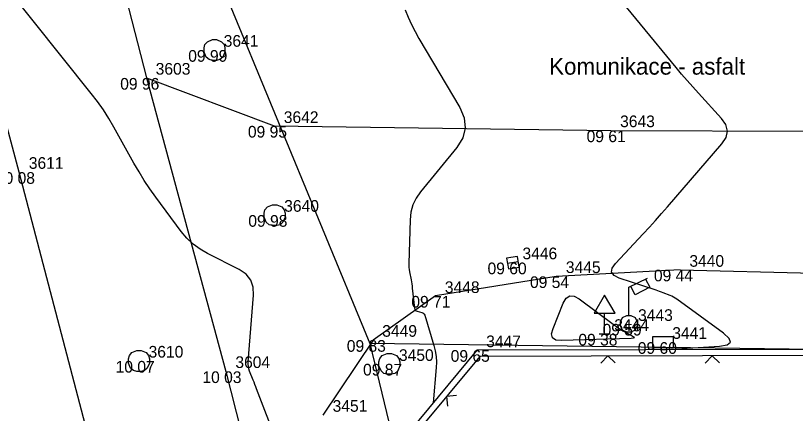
# Model space of a CAD drawing. Extents: x -703403 to -701924, y -1022520 to -1021856.
# Drawn here: x -702667.24 to -702648.55, y -1022343.16 to -1022333.61 of the extents above; entities that cross this region are included whole.
import ezdxf

# ---------------------------------------------------------------- set-up
doc = ezdxf.new("R2010")
doc.units = 0
for name, color, linetype in [('Ex_Major Contours', 7, 'Continuous'), ('Ex_Minor Contours', 7, 'Continuous'), ('Z_body', 7, 'Continuous'), ('Z_body_cisla', 7, 'Continuous'), ('Z_body_vysky_redukovane', 7, 'Continuous'), ('Z_dopravni_znacky', 7, 'Continuous'), ('Z_katastr_hranice', 7, 'Continuous'), ('Z_komunikace', 7, 'Continuous'), ('Z_komunikace_osa', 7, 'Continuous'), ('Z_pilire', 7, 'Continuous'), ('Z_ploty', 7, 'Continuous'), ('Z_ploty_znacky', 7, 'Continuous'), ('Z_popisy', 7, 'Continuous'), ('Z_site_kanalizace_znaky', 7, 'Continuous'), ('Z_site_vo_znaky', 7, 'Continuous'), ('Z_vdz13_prerusovana', 7, 'Continuous'), ('Z_VDZ_25_prerus', 7, 'Continuous')]:
    doc.layers.add(name, color=color, linetype=linetype)

# ---------------------------------------------------------------- blocks, each defined once
blk = doc.blocks.new('POINT_DISPLAY')
blk.add_line((0, 0), (0, 0))
blk = doc.blocks.new('Z13')
for p, q in [((0, 0.88), (0.45, 1.1)), ((0.4, 1.07), (0.5, 0.88)), ((0, 0.2), (0, 0.88)), ((0.15, 0.7), (0.05, 0.9)), ((0.5, 0.88), (0.15, 0.7)), ((-0.15, 0.15), (-0.05, 0.2)), ((-0.05, 0.2), (0.05, 0.2)), ((0.05, 0.2), (0.15, 0.15)), ((-0.2, 0.05), (-0.15, 0.15)), ((-0.2, -0.05), (-0.2, 0.05)), ((0.15, 0.15), (0.2, 0.05)), ((0.2, 0.05), (0.2, -0.05)), ((-0.15, -0.15), (-0.2, -0.05)), ((-0.05, -0.2), (-0.15, -0.15)), ((0.15, -0.15), (0.05, -0.2)), ((0.2, -0.05), (0.15, -0.15)), ((0.05, -0.2), (-0.05, -0.2))]:
    blk.add_line(p, q)
blk = doc.blocks.new('Z666')
for p, q in [((-0.25, 0.13), (-0.25, -0.13)), ((0.25, 0.13), (-0.25, 0.13)), ((0.25, -0.13), (0.25, 0.13)), ((-0.25, -0.13), (0.25, -0.13))]:
    blk.add_line(p, q)
blk = doc.blocks.new('Z620')
for p, q in [((-0.23, 0.13), (-0.17, 0.2)), ((-0.17, 0.2), (-0.05, 0.25)), ((-0.05, 0.25), (0.05, 0.25)), ((0.05, 0.25), (0.17, 0.2)), ((0.17, 0.2), (0.23, 0.13)), ((-0.25, 0.05), (-0.23, 0.13)), ((-0.25, -0.05), (-0.25, 0.05)), ((0.23, 0.13), (0.25, 0.05)), ((0.25, 0.05), (0.25, -0.05)), ((-0.2, -0.17), (-0.25, -0.05)), ((-0.13, -0.23), (-0.2, -0.17)), ((0.2, -0.17), (0.13, -0.23)), ((0.25, -0.05), (0.2, -0.17)), ((-0.05, -0.25), (-0.13, -0.23)), ((0.05, -0.25), (-0.05, -0.25)), ((0.13, -0.23), (0.05, -0.25))]:
    blk.add_line(p, q)
blk = doc.blocks.new('Z46260')
for p, q in [((0.13, 0.13), (-0.13, 0.13)), ((-0.13, 0.13), (-0.13, -0.13)), ((0.13, 0), (-0.13, 0)), ((0.13, -0.13), (0.13, 0.13)), ((-0.13, -0.13), (0.13, -0.13))]:
    blk.add_line(p, q)
blk = doc.blocks.new('Z527')
for p, q in [((0, 0.93), (-0.25, 0.5)), ((0.25, 0.5), (0, 0.93)), ((-0.25, 0.5), (0.25, 0.5)), ((0, 0), (0, 0.5)), ((-0.13, 0), (0.13, 0))]:
    blk.add_line(p, q)
blk = doc.blocks.new('Z212')
for p, q in [((-0.17, 0.17), (0, 0)), ((0, 0), (0.17, 0.17))]:
    blk.add_line(p, q)

msp = doc.modelspace()

# ---------------------------------------------------------------- linework, layer by layer
at = {"layer": 'Ex_Major Contours'}
msp.add_lwpolyline([(-702660.969, -1022343.856), (-702661.46, -1022342.572), (-702661.481, -1022342.519), (-702661.501, -1022342.465), (-702661.522, -1022342.412), (-702661.543, -1022342.358), (-702661.628, -1022342.144), (-702661.646, -1022342.09), (-702661.658, -1022342.036), (-702661.663, -1022341.98), (-702661.661, -1022341.923), (-702661.532, -1022340.323), (-702661.541, -1022340.126), (-702661.601, -1022339.958), (-702661.713, -1022339.819), (-702661.877, -1022339.708), (-702662.635, -1022339.325), (-702662.817, -1022339.219), (-702662.983, -1022339.095), (-702663.133, -1022338.953), (-702663.267, -1022338.792), (-702663.878, -1022337.968), (-702664.018, -1022337.771), (-702664.152, -1022337.57), (-702664.279, -1022337.366), (-702664.4, -1022337.156), (-702664.879, -1022336.292), (-702665.002, -1022336.081), (-702665.134, -1022335.875), (-702665.274, -1022335.674), (-702665.422, -1022335.48), (-702667.51, -1022332.859)], dxfattribs=at)
at = {"layer": 'Ex_Minor Contours'}
for points in [[(-702651.778, -1022341.631), (-702650.365, -1022341.542), (-702650.183, -1022341.512), (-702650.107, -1022341.451), (-702650.138, -1022341.358), (-702650.275, -1022341.234), (-702651.39, -1022340.416), (-702651.428, -1022340.391), (-702651.467, -1022340.368), (-702651.507, -1022340.347), (-702651.548, -1022340.329), (-702651.717, -1022340.263), (-702651.76, -1022340.247), (-702651.802, -1022340.231), (-702651.845, -1022340.216), (-702651.888, -1022340.202), (-702652.77, -1022339.912), (-702652.896, -1022339.85), (-702652.953, -1022339.771), (-702652.941, -1022339.673), (-702652.86, -1022339.558), (-702652.195, -1022338.85), (-702652.046, -1022338.69), (-702651.899, -1022338.528), (-702651.754, -1022338.365), (-702651.611, -1022338.2), (-702650.309, -1022336.69), (-702650.21, -1022336.536), (-702650.178, -1022336.383), (-702650.214, -1022336.23), (-702650.318, -1022336.079), (-702650.87, -1022335.476), (-702651.007, -1022335.324), (-702651.142, -1022335.171), (-702651.275, -1022335.015), (-702651.405, -1022334.858), (-702653.116, -1022332.77)], [(-702657.902, -1022333.475), (-702657.83, -1022333.651), (-702657.751, -1022333.824), (-702657.665, -1022333.994), (-702657.571, -1022334.16), (-702656.59, -1022335.822), (-702656.483, -1022336.07), (-702656.46, -1022336.312), (-702656.519, -1022336.548), (-702656.663, -1022336.777), (-702657.53, -1022337.839), (-702657.636, -1022337.992), (-702657.714, -1022338.156), (-702657.762, -1022338.33), (-702657.782, -1022338.516), (-702657.812, -1022339.56), (-702657.812, -1022339.61), (-702657.81, -1022339.66), (-702657.805, -1022339.709), (-702657.797, -1022339.758), (-702657.76, -1022339.954), (-702657.751, -1022340.004), (-702657.744, -1022340.053), (-702657.737, -1022340.102), (-702657.731, -1022340.152), (-702657.676, -1022340.636), (-702657.67, -1022340.662), (-702657.658, -1022340.682), (-702657.639, -1022340.697), (-702657.614, -1022340.707), (-702657.503, -1022340.734), (-702657.478, -1022340.743), (-702657.457, -1022340.758), (-702657.442, -1022340.777), (-702657.431, -1022340.802), (-702657.213, -1022341.529), (-702657.18, -1022341.66), (-702657.16, -1022341.793), (-702657.152, -1022341.926), (-702657.158, -1022342.061), (-702657.23, -1022342.905)]]:
    msp.add_lwpolyline(points, dxfattribs=at)
msp.add_lwpolyline([(-702654.289, -1022341.399), (-702654.368, -1022341.345), (-702654.391, -1022341.253), (-702654.358, -1022341.121), (-702654.113, -1022340.517), (-702654.043, -1022340.397), (-702653.955, -1022340.339), (-702653.851, -1022340.344), (-702653.729, -1022340.41), (-702652.888, -1022341.038), (-702652.838, -1022341.075), (-702652.786, -1022341.11), (-702652.734, -1022341.143), (-702652.681, -1022341.174), (-702652.464, -1022341.298), (-702652.425, -1022341.325), (-702652.414, -1022341.345), (-702652.433, -1022341.357), (-702652.481, -1022341.363), (-702654.154, -1022341.413)], close=True, dxfattribs=at)
at = {"layer": 'Z_katastr_hranice'}
for p, q in [((-702668.61, -1022317.56), (-702658.75, -1022341.48)), ((-702629.64, -1022341.87), (-702658.75, -1022341.48)), ((-702658.75, -1022341.48), (-702651.59, -1022370.87))]:
    msp.add_line(p, q, dxfattribs=at)
at = {"layer": 'Z_komunikace'}
for p, q in [((-702651.31, -1022339.71), (-702654.28, -1022339.87)), ((-702651.31, -1022339.71), (-702644.5, -1022339.89)), ((-702654.28, -1022339.87), (-702657.17, -1022340.34)), ((-702657.17, -1022340.34), (-702658.67, -1022341.4)), ((-702658.67, -1022341.4), (-702659.87, -1022343.2))]:
    msp.add_line(p, q, dxfattribs=at)
at = {"layer": 'Z_komunikace_osa'}
for p, q in [((-702664.1, -1022335.11), (-702661.04, -1022336.26)), ((-702661.04, -1022336.26), (-702652.97, -1022336.37)), ((-702652.97, -1022336.37), (-702644.72, -1022336.4))]:
    msp.add_line(p, q, dxfattribs=at)
at = {"layer": 'Z_ploty'}
for p, q in [((-702656.18, -1022341.64), (-702658.28, -1022344.17)), ((-702646.79, -1022341.62), (-702656.18, -1022341.64)), ((-702646.79, -1022341.77), (-702656.11, -1022341.79)), ((-702656.11, -1022341.79), (-702658.12, -1022344.21))]:
    msp.add_line(p, q, dxfattribs=at)
at = {"layer": 'Z_vdz13_prerusovana'}
for p, q in [((-702667.15, -1022337.37), (-702668.59, -1022332.01)), ((-702665.25, -1022344.64), (-702667.15, -1022337.37))]:
    msp.add_line(p, q, dxfattribs=at)
at = {"layer": 'Z_VDZ_25_prerus'}
for p, q in [((-702665.97, -1022327.85), (-702664.1, -1022335.11)), ((-702664.1, -1022335.11), (-702662.2, -1022342.15)), ((-702662.2, -1022342.15), (-702661.45, -1022345.12))]:
    msp.add_line(p, q, dxfattribs=at)

# ---------------------------------------------------------------- block references
at = {"layer": 'Z_body'}
for p in [(-702662.47, -1022334.44), (-702664.1, -1022335.11), (-702661.04, -1022336.26), (-702652.97, -1022336.37), (-702667.15, -1022337.37), (-702661.03, -1022338.4), (-702655.32, -1022339.54), (-702651.31, -1022339.71), (-702654.28, -1022339.87), (-702657.17, -1022340.34), (-702652.54, -1022341.01), (-702658.67, -1022341.4), (-702653.12, -1022341.25), (-702651.72, -1022341.45), (-702656.18, -1022341.64), (-702664.28, -1022341.9), (-702662.2, -1022342.15), (-702658.28, -1022341.97)]:
    msp.add_blockref('POINT_DISPLAY', p, dxfattribs=at)
at = {"layer": 'Z_dopravni_znacky'}
msp.add_blockref('Z527', (-702653.12, -1022341.25), dxfattribs=at)
at = {"layer": 'Z_pilire'}
msp.add_blockref('Z666', (-702651.72, -1022341.45), dxfattribs=at)
at = {"layer": 'Z_ploty_znacky'}
for p, rotation in [((-702653.04, -1022341.78), -179.90000000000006), ((-702650.54, -1022341.78), -179.90000000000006), ((-702656.91, -1022342.75), -129.69999999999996)]:
    msp.add_blockref('Z212', p, dxfattribs=dict(at, rotation=rotation))
at = {"layer": 'Z_site_kanalizace_znaky'}
for p in [(-702662.47, -1022334.44), (-702661.03, -1022338.4), (-702664.28, -1022341.9), (-702658.28, -1022341.97)]:
    msp.add_blockref('Z620', p, dxfattribs=at)
at = {"layer": 'Z_site_kanalizace_znaky', "rotation": 9}
msp.add_blockref('Z46260', (-702655.32, -1022339.54), dxfattribs=at)
at = {"layer": 'Z_site_vo_znaky'}
msp.add_blockref('Z13', (-702652.54, -1022341.01), dxfattribs=at)

# ---------------------------------------------------------------- texts
at = {"layer": 'Z_body_cisla'}
for s, p in [('3641', (-702662.25, -1022334.36)), ('3603', (-702663.88, -1022335.03)), ('3642', (-702660.81, -1022336.19)), ('3643', (-702652.75, -1022336.29)), ('3611', (-702666.92, -1022337.29)), ('3640', (-702660.8, -1022338.32)), ('3446', (-702655.09, -1022339.46)), ('3445', (-702654.05, -1022339.79)), ('3440', (-702651.09, -1022339.64)), ('3448', (-702656.95, -1022340.27)), ('3443', (-702652.32, -1022340.94)), ('3444', (-702652.89, -1022341.18)), ('3449', (-702658.45, -1022341.32)), ('3441', (-702651.5, -1022341.37)), ('3447', (-702655.96, -1022341.57)), ('3610', (-702664.05, -1022341.82)), ('3450', (-702658.05, -1022341.9)), ('3604', (-702661.97, -1022342.07)), ('3451', (-702659.64, -1022343.12))]:
    msp.add_text(s, height=0.28, dxfattribs=at).set_placement(p)
at = {"layer": 'Z_body_vysky_redukovane'}
for s, p in [('09 99', (-702663.1, -1022334.72)), ('09 96', (-702664.73, -1022335.39)), ('09 95', (-702661.67, -1022336.54)), ('09 61', (-702653.553, -1022336.65)), ('10 08', (-702667.71, -1022337.65)), ('09 98', (-702661.66, -1022338.68)), ('09 60', (-702655.927, -1022339.82)), ('09 44', (-702651.94, -1022339.99)), ('09 54', (-702654.91, -1022340.15)), ('09 71', (-702657.753, -1022340.62)), ('09 59', (-702653.17, -1022341.29)), ('09 83', (-702659.3, -1022341.68)), ('09 38', (-702653.75, -1022341.53)), ('09 60', (-702652.327, -1022341.73)), ('09 65', (-702656.81, -1022341.92)), ('10 07', (-702664.84, -1022342.18)), ('09 87', (-702658.91, -1022342.25)), ('10 03', (-702662.76, -1022342.43))]:
    msp.add_text(s, height=0.28, dxfattribs=at).set_placement(p)
at = {"layer": 'Z_popisy'}
msp.add_text('Komunikace - asfalt', height=0.4, dxfattribs=at).set_placement((-702654.45, -1022335.03))

doc.saveas('drawing.dxf')
